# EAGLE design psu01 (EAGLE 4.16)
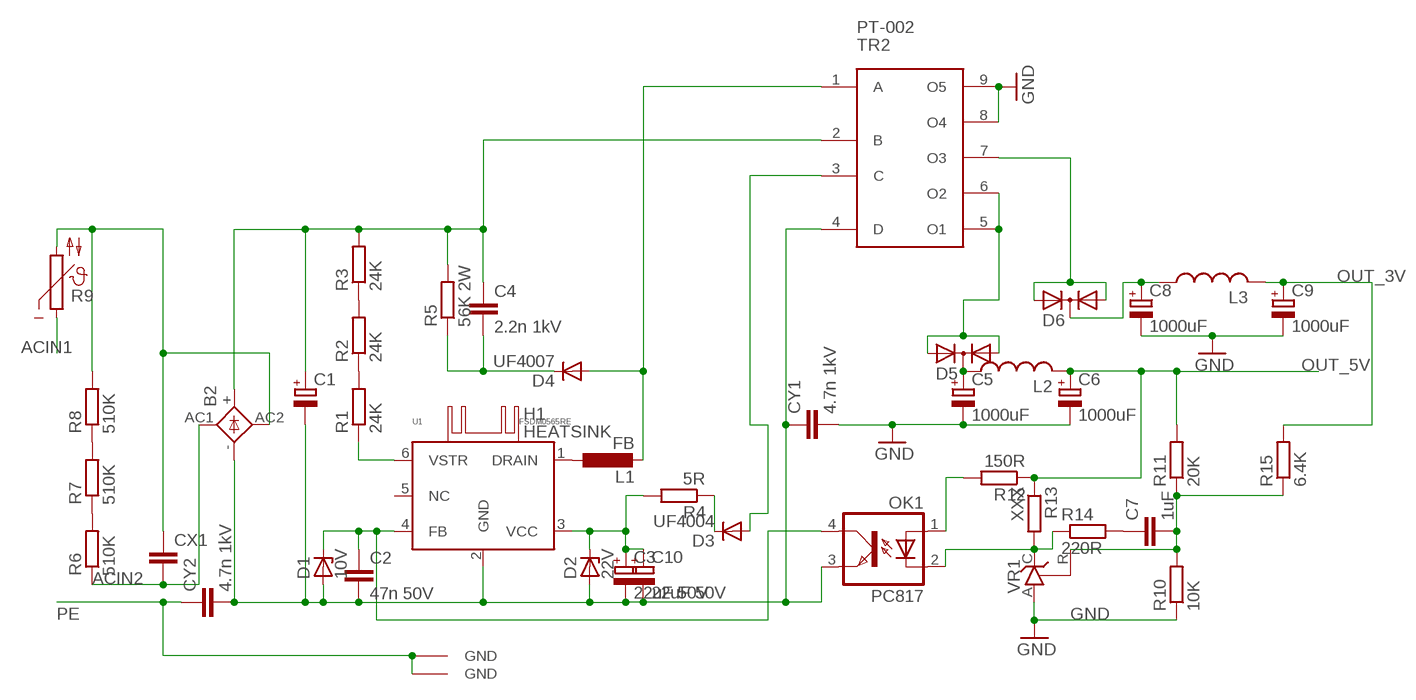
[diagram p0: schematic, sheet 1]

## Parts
B2  2KBB-R  [2KBB-R]
C1  CPOL-EUE7.5-16  [E7,5-16]
C2  47n 50V  C-EU025-024X044  [C025-024X044]
C3  22uF 50V  CPOL-EUE5-4  [E5-4]
C4  2.2n 1kV  C-EU050-024X044  [C050-024X044]
C5  1000uF  CPOL-EUE5-6  [E5-6]
C6  1000uF  CPOL-EUE5-6  [E5-6]
C7  1uF  C-EU025-024X044  [C025-024X044]
C8  1000uF  CPOL-EUE5-6  [E5-6]
C9  1000uF  CPOL-EUE5-6  [E5-6]
C10  22uF 50V  CPOL-EUE5-4  [E5-4]
CX1  CXXC10B5  [XC10B5]
CY1  4.7n 1kV  CYYC7B5  [YC7B5]
CY2  4.7n 1kV  CYYC7B5  [YC7B5]
D1  10V  ZENER-DIODEDO41Z10  [DO41Z10]
D2  22V  ZENER-DIODEDO41Z10  [DO41Z10]
D3  UF4004  DIODE-DO41-10  [DO41-10]
D4  UF4007  DIODE-DO41-10  [DO41-10]
D5  DIODE-2AC|CATO220V  [TO220ABS]
D6  DIODE-2AC|CATO220V  [TO220ABS]
H1  HEATSINK  [HSINK1]
L1  FB  L-EU0207/10  [0207/10]
L2  L-US0207/5V  [0207/5V]
L3  L-US0207/5V  [0207/5V]
OK1  PC817  [DIL04]
R1  24K  R-EU_M1206  [M1206]
R2  24K  R-EU_M1206  [M1206]
R3  24K  R-EU_M1206  [M1206]
R4  5R  R-EU_0207/10  [0207/10]
R5  56K 2W  R-EU_0309/12  [0309/12]
R6  510K  R-EU_M1206  [M1206]
R7  510K  R-EU_M1206  [M1206]
R8  510K  R-EU_M1206  [M1206]
R9  B57164  [B57164]
R10  10K  R-EU_0207/10  [0207/10]
R11  20K  R-EU_0207/10  [0207/10]
R12  150R  R-EU_0207/10  [0207/10]
R13  XXX  R-EU_0207/10  [0207/10]
R14  220R  R-EU_0207/10  [0207/10]
R15  6.4K  R-EU_0207/12  [0207/12]
TR2  PT-002  [PT-002]
U1  FSDM0565RE  [TO220A06REVB]
VR1  TL431CLP  [TO92-CLP]

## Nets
ACIN1: R9.1
ACIN2: B2.AC1 CX1.2 R6.1
GND: C5.- C6.- C8.- C9.- CY1.2 R10.1 TR2.8(O4) TR2.9(O5) VR1.A
MINUSAS: B2.- C1.- C2.2 C3.- C10.- CY1.1 CY2.2 D1.A D2.A OK1.3(EMIT) TR2.4(D) U1.2(GND)
N$1: R1.2 R2.1
N$2: R2.2 R3.1
N$3: R1.1 U1.6(VSTR)
N$4: D3.C R4.1
N$5: C8.+ D6.C L3.1
N$6: C2.1 D1.C OK1.4(COL) U1.4(FB)
N$7: D3.A TR2.3(C)
N$8: L1.1 U1.1(DRAIN)
N$10: C4.2 D4.C R5.1
N$11: C5.+ D5.C L2.1
N$12: D4.A L1.2 TR2.1(A)
N$13: D6.A1 D6.A2 TR2.7(O3)
N$14: D5.A1 D5.A2 TR2.5(O1) TR2.6(O2)
N$16: B2.AC2 CX1.1 R8.2 R9.2
N$17: R6.2 R7.1
N$18: R7.2 R8.1
N$20: OK1.2(C) R13.2 R14.1 VR1.C
N$23: OK1.1(A) R12.2
N$25: C7.2 R10.2 R11.1 R15.1 VR1.R
N$28: C7.1 R14.2
OUT_3V: C9.+ L3.2 R15.2
OUT_5V: C6.+ L2.2 R11.2 R12.1 R13.1
PE: CY2.1 H1.P$1(GND) H1.P$2(GND)
PLIUSAS: B2.+ C1.+ C4.1 R3.2 R5.2 TR2.2(B)
VCC: C3.+ C10.+ D2.C R4.2 U1.3(VCC)
Unconnected: U1.5(NC)

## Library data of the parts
B2 = rectifier:2KBB-R: RECTIFIER grid 3 x 5 mm
C1 C3 C5 C6 C8-C10 = rcl:CPOL-EU: POLARIZED CAPACITOR, European symbol
C2 C4 C7 = rcl:C-EU: CAPACITOR, European symbol
CX1 = rcl:CX: X CAPACITOR
CY1 CY2 = rcl:CY: Y CAPACITOR
D1 D2 = diode:ZENER-DIODE: Z-Diode
D3 D4 = diode:DIODE-: DIODE
D5 D6 = diode:DIODE-2AC|CA: Dual DIODE Anode-Cathode|Cathode-Anode
H1 = LevoROMS:HEATSINK: various heatsinks
L1 = rcl:L-EU: INDUCTOR, European symbol
L2 L3 = rcl:L-US: INDUCTOR, American symbol
OK1 = optocoupler:PC817: SHARP OPTO COUPLER
R1-R8 R10-R15 = rcl:R-EU_: RESISTOR, European symbol
R9 = ptc-ntc:B57164: SIEMENS NTC
TR2 = LG-trafo:PT-002
U1 = LevoROMS:FSDM0565RE: FSDM0565RE are an integrated Pulse width Modulator ans Sense FET specially designed for high-performance offline Switchmode power suplies with minimal external components.
VR1 = v-reg:TL431CLP: VOLTAGE REGULATOR

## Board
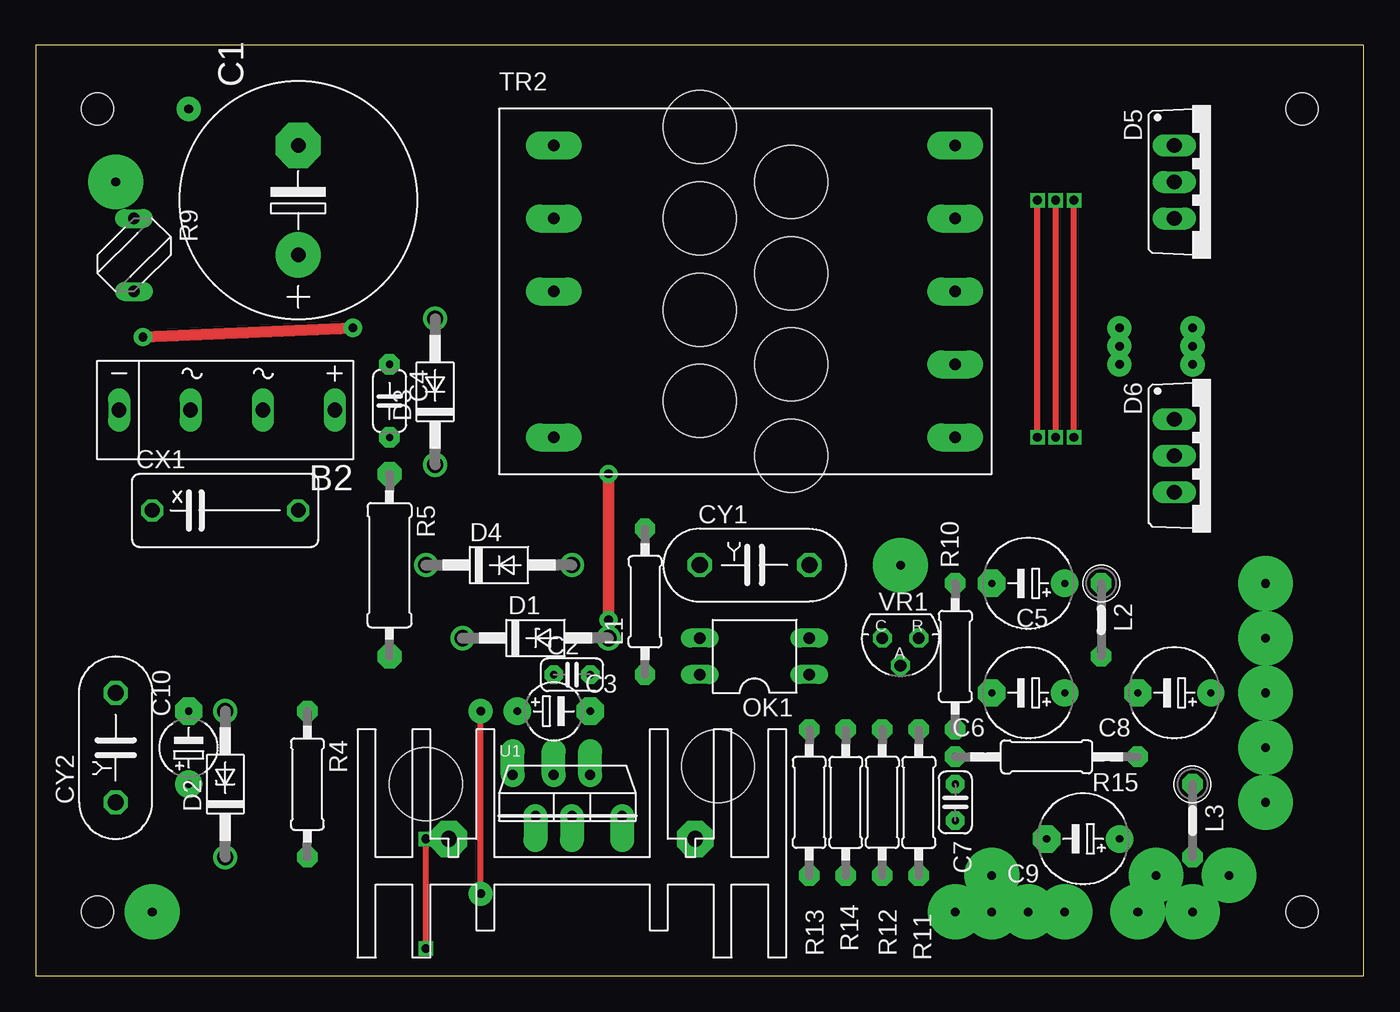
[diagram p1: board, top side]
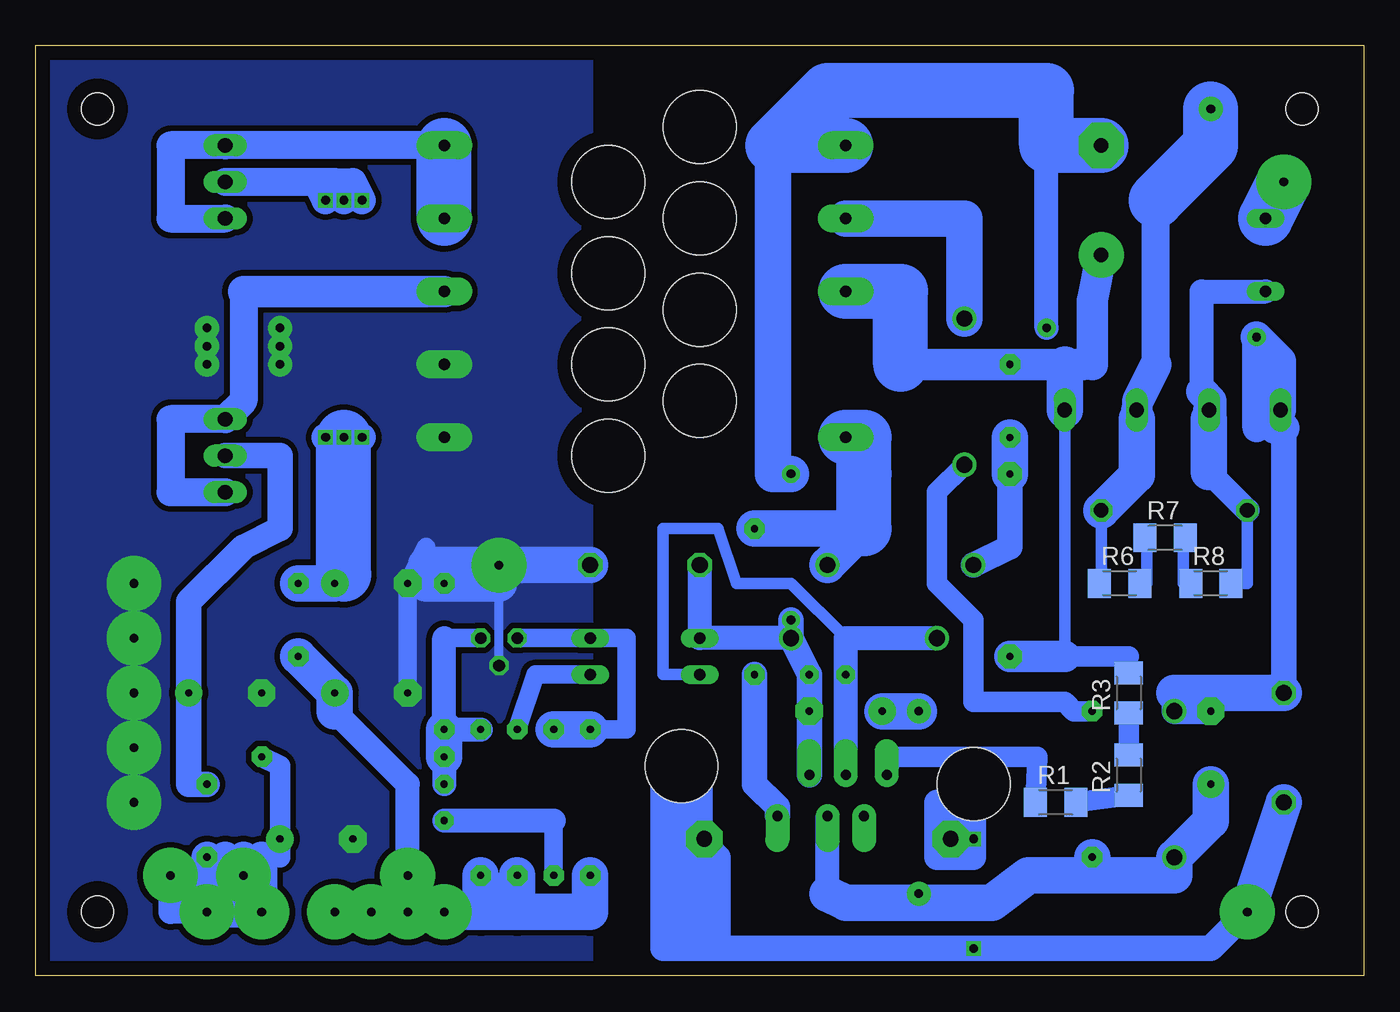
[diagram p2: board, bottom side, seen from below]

Size 92.38 x 64.76 mm. Coordinates in mm from the lower left corner, seen from the top.
Outline: 0,0 92.38,0 92.38,64.76 0,64.76 0,0
Copper layers (1*16): Top 0.035mm / dielectric 1.5mm / Bottom 0.035mm
Design rules "default": minimum track width 10mil, minimum drill 24mil, track to track 8mil, track to pad 8mil, pad to pad 8mil, via to via 8mil, smd to smd 8mil, copper to edge 40mil, drill to drill 8mil, minimum pad ring 10mil, minimum via ring 8mil, stop-mask expansion 4mil, vias tented up to drill 0mil, thermal gap 10mil
Holes 2.2 mm at 4.28,4.44 88.1,4.44 88.1,60.32 4.28,60.32
Holes 5.08 mm at 46.19,59.05 46.19,52.7 46.19,46.35 46.19,40 52.54,36.19 52.54,42.54 52.54,48.89 52.54,55.24 47.46,14.6 27.14,13.33

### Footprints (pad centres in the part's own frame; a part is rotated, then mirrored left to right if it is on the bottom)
2KBB-R = drill 1.016 long: + -7.62,0; - 7.391,0; AC1 -2.616,0; AC2 2.413,0
E7,5-16 = drill 1.016 pad 3.15 round: + -3.81,0 | drill 1.016 pad 3.15 octagon: - 3.81,0
C025-024X044 = drill 0.5 pad 1.27 octagon: 1 -1.27,0; 2 1.27,0
E5-4 = drill 0.5 pad 1.905 round: + -2.54,0 | drill 0.5 pad 1.905 octagon: - 2.54,0
C050-024X044 = drill 0.5 pad 1.422 octagon: 1 -2.54,0; 2 2.54,0
E5-6 = drill 0.5 pad 1.905 round: + -2.54,0 | drill 0.5 pad 1.905 octagon: - 2.54,0
XC10B5 = drill 1.016 octagon: 1 -5.08,0; 2 5.08,0
YC7B5 = drill 1.118 octagon: 1 -3.81,0; 2 3.81,0
DO41Z10 = drill 1.118 round: A 5.08,0; C -5.08,0
DO41-10 = drill 1.118 round: A 5.08,0; C -5.08,0
TO220ABS = drill 1.016 long: A1 -2.54,-2.54; A2 2.54,-2.54; C 0,-2.54
HSINK1 = drill 1.1 pad 2.54 octagon: P$1 -8.572,0; P$2 8.572,0
0207/10 = drill 0.5 pad 1.422 octagon: 1 -5.08,0; 2 5.08,0
0207/5V = drill 0.5 pad 1.422 octagon: 1 -2.54,0; 2 2.54,0
DIL04 = drill 0.813 long: 1 -1.27,-3.81; 2 1.27,-3.81; 3 1.27,3.81; 4 -1.27,3.81
M1206 = smd 1.6 x 2: 1 -1.4,0; 2 1.4,0
0309/12 = drill 0.5 pad 1.676 octagon: 1 -6.35,0; 2 6.35,0
B57164 = drill 0.813 long: 1 -2.54,0; 2 2.54,0
0207/12 = drill 0.5 pad 1.422 octagon: 1 -6.35,0; 2 6.35,0
PT-002 = drill 0.8 pad 1.93 long: 1 -3.81,-12.7; 2 -3.81,-2.54; 3 -3.81,2.54; 4 -3.81,7.62; 5 24.13,7.62; 6 24.13,2.54; 7 24.13,-2.54; 8 24.13,-7.62; 9 24.13,-12.7
TO220A06REVB = drill 0.7 pad 1.676 offset: 1 3.493,-1.587; 2 1.27,1.27; 3 0,-1.587; 4 -1.27,1.27; 5 -2.54,-1.587; 6 -4.128,1.27
TO92-CLP = drill 0.813 octagon: A 0,1.905; C 1.27,0; R -1.27,0

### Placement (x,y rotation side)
B2  13.17,39.37 180 top
C1  18.25,53.97 90 top
C2  37.3,20.95 0 top
C3  36.03,18.41 0 top
C4  24.6,40 270 top
C5  69.05,27.3 180 top
C6  69.05,19.68 180 top
C7  63.97,12.06 90 top
C8  79.21,19.68 180 top
C9  72.86,9.52 180 top
C10  10.63,15.87 90 top
CX1  13.17,32.38 0 top
CY1  50,28.57 0 top
CY2  5.55,15.87 90 top
D1  34.76,23.49 0 top
D2  13.17,13.33 90 top
D3  27.77,40.64 90 top
D4  32.22,28.57 0 top
D5  81.75,55.24 270 top
D6  81.75,36.19 270 top
H1  37.3,9.52 0 top
L1  42.38,26.03 90 top
L2  74.13,24.76 270 top
L3  80.48,10.79 270 top
OK1  50,22.22 90 top
R1  21.42,12.06 0 bottom
R2  16.34,13.97 90 bottom
R3  16.34,19.68 90 bottom
R4  18.88,13.33 270 top
R5  24.6,28.57 270 top
R6  16.98,27.3 0 bottom
R7  13.81,30.47 0 bottom
R8  10.63,27.3 0 bottom
R9  6.82,50.16 270 top
R10  63.97,22.22 270 top
R11  61.43,12.06 270 top
R12  58.89,12.06 90 top
R13  53.81,12.06 90 top
R14  56.35,12.06 270 top
R15  70.32,15.24 0 top
TR2  39.84,50.16 0 top
U1  37.3,12.7 0 top
VR1  60.16,23.49 180 top

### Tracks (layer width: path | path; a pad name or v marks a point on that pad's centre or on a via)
ACIN1  (via drill 0.6 pad 3.81)
  Bottom 3.81: R9.1 v5.55,55.24
ACIN2  (via drill 0.6 pad 1.68)
  Bottom 0.813: R6.1 18.25,27.3 CX1.2
  Bottom 1.93: 14.44,42.54 14.44,53.97 | 15.79,38.73 15.71,38.73 15.71,40
  Bottom 2.184: 15.79,38.73 B2.AC1 | 15.71,40 14.44,42.54
  Bottom 2.54: 15.79,38.73 15.79,34.84 CX1.2
  Bottom 3.81: v10.63,60.32 10.63,57.78 14.44,53.97
GND  (via drill 0.6 pad 1.68, 0.6 pad 3.81)
  Bottom 0.61: VR1.A 60.16,27.3 v60.16,28.57
  Bottom 1.27: R10.1 65.24,27.3 65.24,28.57 65.24,29.84 C5.- C6.-
  Bottom 2.54: 65.24,28.57 v60.16,28.57 CY1.2 | 60.16,27.3 65.24,27.3
  other vias: 85.56,27.3 85.56,23.49 85.56,19.68 85.56,15.87 85.56,12.06 75.4,45.08 75.4,43.81 75.4,42.54 80.48,45.08 80.48,43.81 80.48,42.54
  pour Bottom (isolate 0.406, no thermals): 53.81,69.21 53.81,-4.45 100.8,-4.45 100.8,69.21
MINUSAS  (via drill 0.6 pad 1.27)
  Top 0.813: v39.84,34.92 v39.84,24.76 | v7.46,44.45 v22.06,45.08
  Bottom 0.813: 6.95,38.6 6.18,38.1 7.46,38.1
  Bottom 1.676: CY1.1 OK1.3 D1.A | v22.06,45.08 22.06,57.78
  Bottom 1.778: 6.18,38.1 6.95,38.48 | CY2.2 5.55,38.1 | C2.2 C3.- | C3.- U1.2 | C2.2 D1.A v39.84,24.76 | 13.17,19.68 D2.A C10.- | C2.2 C3.-
  Bottom 1.93: 7.46,38.1 v7.46,44.45
  Bottom 2.184: 5.55,38.1 6.18,38.1 | 6.95,38.48 6.95,38.6 | B2.- 5.78,42.77 v7.46,44.45
  Bottom 2.54: v39.84,34.92 41.11,34.92 41.11,57.78 | CY2.2 13.17,19.68
  Bottom 3.81: C1.- 22.06,57.78 22.06,61.59 37.3,61.59 41.11,57.78 TR2.4
N$1
  Bottom 1.422: R2.1 R1.2
N$2
  Bottom 1.422: R2.2 R3.1
N$3
  Bottom 1.422: R1.1 22.7,15.24 32.85,15.24 U1.6
N$4
  Bottom 1.422: R4.1 20.15,18.41 20.79,19.04 27.14,19.04 27.14,24.76 29.68,27.3 29.68,33.65 D3.C
N$5
  Bottom 1.778: D6.C 75.4,36.19 75.4,31.11 77.94,29.84 81.75,26.03 C8.+ 81.75,13.33 L3.1
N$6
  Bottom 0.813: OK1.4 48.73,20.95 48.73,31.11 44.92,31.11 43.65,27.3 39.84,27.3 36.03,23.49
  Bottom 1.676: U1.4 C2.1 36.03,23.49 D1.C
N$7
  Bottom 2.54: D3.A 27.77,52.7 TR2.3
N$8
  Bottom 1.778: U1.1 40.79,11.74 42.38,13.33 L1.1
N$10
  Bottom 1.778: D4.C 24.6,29.84 R5.1
  Bottom 2.54: R5.1 C4.2
N$11  (via drill 0.6)
  Top 0.406: v69.69,37.46 v69.69,53.97 | v70.95,37.46 v70.95,53.97 | v72.22,37.46 v72.22,53.97
  Bottom 1.93: 71.59,55.24 70.32,55.24 v69.69,53.97 | 71.59,55.24 72.86,55.24 | 72.86,55.24 D5.C | v70.95,53.97 71.59,55.24 | v72.22,53.97 72.86,55.24 | 70.95,27.93 C5.+ | v69.69,37.46 v70.95,37.46 v72.22,37.46
  Bottom 2.54: C5.+ L2.1
  Bottom 3.81: 70.95,27.93 v70.95,37.46
N$12
  Bottom 2.54: D4.A 34.76,31.11 L1.2
  Bottom 3.81: 34.76,31.11 34.76,34.92 34.76,37.46 TR2.1
N$13
  Bottom 1.93: 77.94,47.62 77.94,40 D6.A1 83.02,38.73 83.02,33.65 D6.A2
  Bottom 2.184: TR2.7 77.94,47.62
N$14
  Bottom 1.93: D5.A2 83.02,52.7 83.02,57.78 D5.A1 TR2.5
  Bottom 3.81: TR2.6 TR2.5
N$16
  Bottom 0.813: R8.2 8.09,27.3 CX1.1
  Bottom 1.676: R9.2 11.27,47.62 11.27,40.64 | CX1.1 10.76,35.05 | 10.76,38.73 10.63,38.73
  Bottom 2.184: 10.76,38.73 B2.AC2 | 11.27,40.64 10.63,40 10.63,38.73
  Bottom 2.54: 10.76,35.05 10.76,38.73
N$17
  Bottom 0.813: R7.1 15.08,30.47 15.08,27.3 R6.2
N$18
  Bottom 0.813: R7.2 12.54,30.47 12.54,27.3 R8.1
N$20
  Bottom 1.27: R13.2 51.27,17.14 51.27,23.49 OK1.2 VR1.C
  Bottom 2.54: R13.2 R14.1
N$23
  Bottom 1.27: OK1.1 57.62,20.95 R12.2
N$25
  Bottom 1.27: R15.1 R10.2 | 63.97,23.49 VR1.R
  Bottom 1.676: R11.1 R10.2 63.97,23.49 | R15.1 C7.2
  Bottom 2.54: R15.1 R10.2
N$28
  Bottom 1.27: R14.2 56.35,10.79
  Bottom 1.676: 56.35,10.79 C7.1
OUT_3V  (via drill 0.6 pad 3.81)
  Bottom 0.406: 75.4,8.25 76.67,8.25 77.94,8.25 79.21,8.25 L3.2
  Bottom 1.422: 75.4,8.25 C9.+ 75.4,14.6 R15.2
  Bottom 1.676: v83.02,6.98 83.02,4.44 v80.48,4.44
  Bottom 2.184: v76.67,4.44 76.67,8.25 | L3.2 v80.48,4.44 | 77.94,8.25 v77.94,6.98 77.94,4.44 79.21,4.44 79.21,8.25
OUT_5V  (via drill 0.6 pad 3.81)
  Bottom 1.676: 71.59,18.41 66.51,13.33 v66.51,6.98 | v63.97,4.44 v66.51,4.44
  Bottom 2.184: v71.59,4.44 v69.05,4.44 v66.51,4.44
  Bottom 2.54: L2.2 C6.+ 71.59,18.41 | R13.1 53.81,4.44 58.89,4.44 | 58.89,4.44 61.43,4.44 | 61.43,4.44 v63.97,4.44 v66.51,4.44 v66.51,6.98 | 61.43,4.44 R11.2 | 58.89,4.44 R12.1
PE  (via drill 0.6, 0.6 pad 3.81)
  Top 0.406: v27.14,1.9 v27.14,9.52
  Bottom 0.406: 46.19,9.52 H1.P$2 | 28.41,12.06 28.73,11.74
  Bottom 1.778: v8.09,4.44 10.63,1.9 v27.14,1.9 44.92,1.9 | 44.92,1.9 44.92,8.25 46.19,9.52 | 28.73,11.74 H1.P$1 | 27.14,12.06 28.41,12.06 29.68,12.06 29.68,8.25 27.14,8.25 27.14,12.06 | v27.14,9.52 27.14,12.06 | 46.19,13.33 46.19,3.17 47.46,3.17 47.46,13.33 48.73,13.33 48.73,1.9 44.92,1.9
  Bottom 2.54: v8.09,4.44 CY2.1
PLIUSAS
  Bottom 0.254: 19.52,42.54 18.88,42.54
  Bottom 0.813: R3.2 16.34,22.22 | 20.79,22.22 B2.+
  Bottom 1.422: 16.34,22.22 20.79,22.22
  Bottom 2.184: 18.88,42.54 18.88,46.98 C1.+ | 19.52,42.54 20.79,42.54 C4.1 32.22,42.54 | 20.79,22.22 R5.2
  Bottom 2.54: B2.+ 20.79,42.54
  Bottom 3.81: 32.22,42.54 32.22,47.62 TR2.2
VCC  (via drill 0.6 pad 1.68)
  Top 0.406: v30.95,5.71 v30.95,18.41
  Bottom 0.406: v30.95,5.71 30.95,4.44 32.85,4.44 33.49,5.08
  Bottom 1.422: 19.52,6.98 18.88,7.62
  Bottom 1.676: 37.3,5.71 U1.3
  Bottom 2.54: 37.3,5.71 36.03,5.08 33.49,5.08 25.87,5.08 23.33,6.98 19.52,6.98 13.17,6.98 D2.C 10.63,10.79 C10.+ | 18.88,7.62 R4.2 | v30.95,18.41 C3.+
